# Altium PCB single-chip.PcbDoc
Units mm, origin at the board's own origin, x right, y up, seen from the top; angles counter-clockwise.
Board outline 125 x 86.13 mm, 4 copper layers (Top Layer, POWER, GND, Bottom Layer), stack 0.569 mm thick; 50 components, 172 nets, 486 pads, 32 vias.
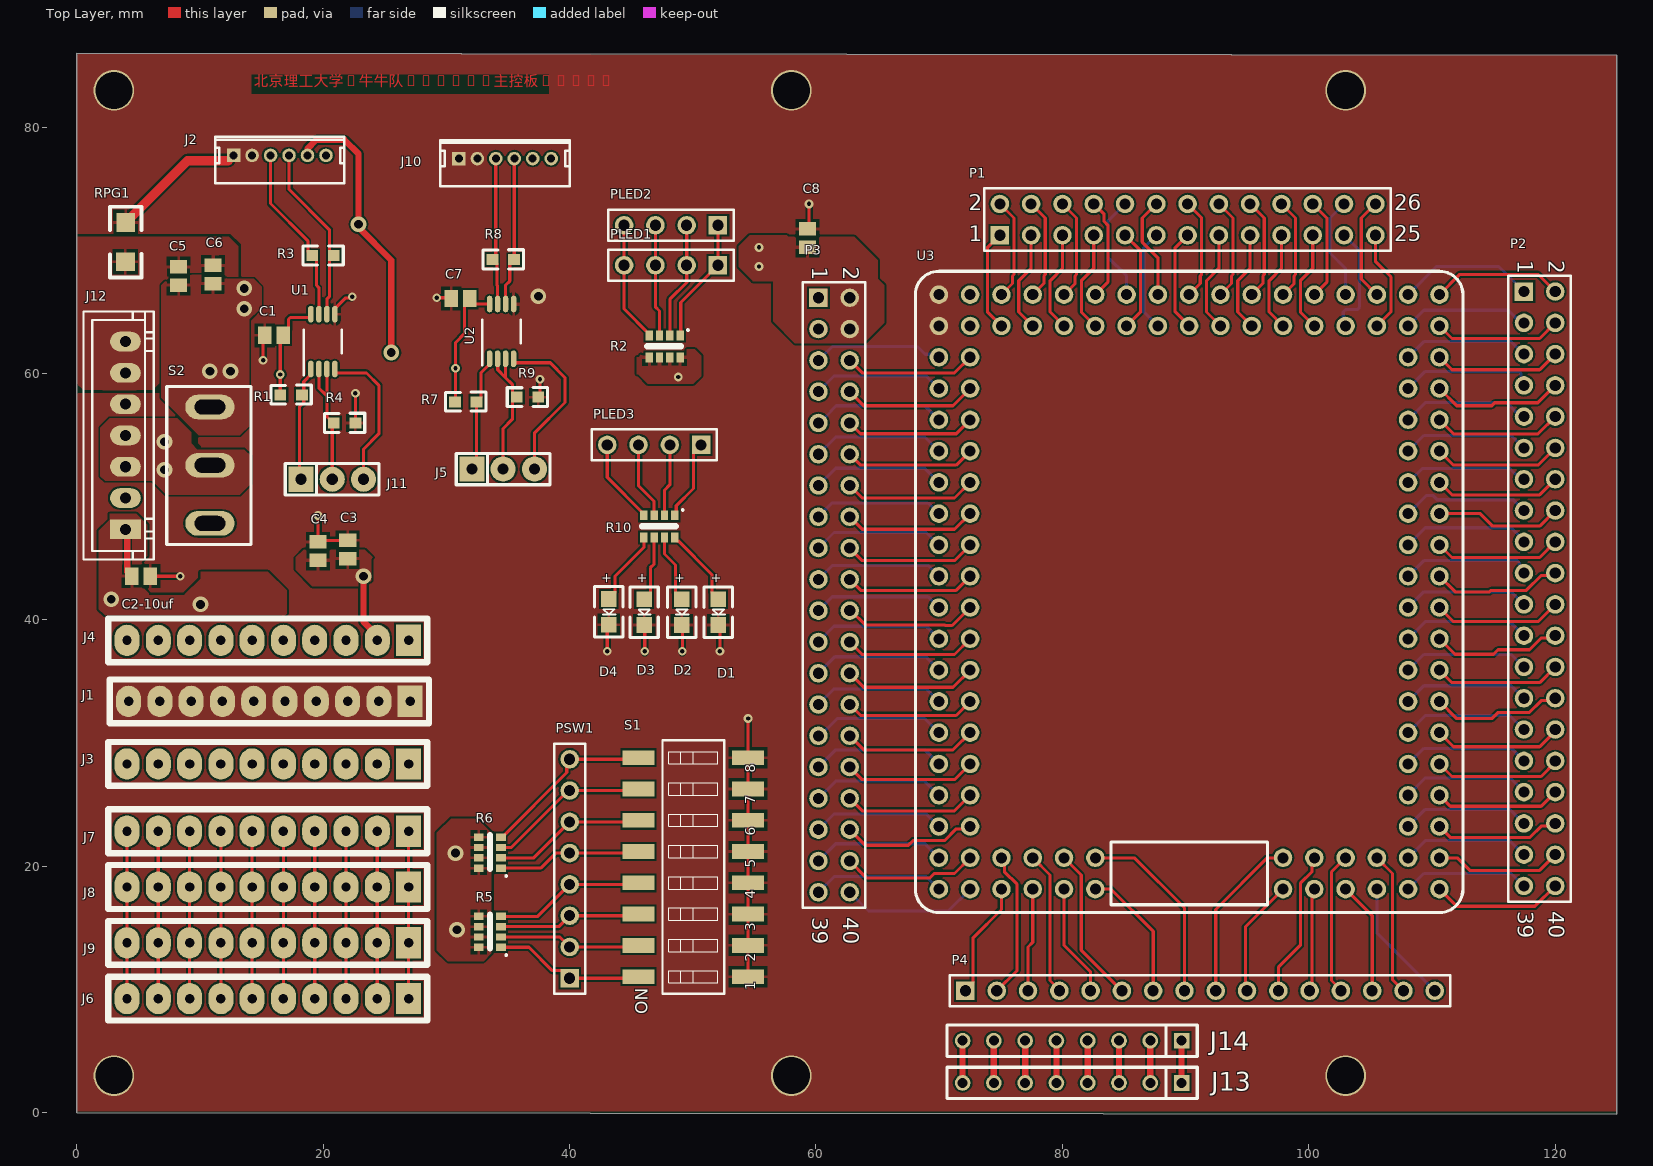
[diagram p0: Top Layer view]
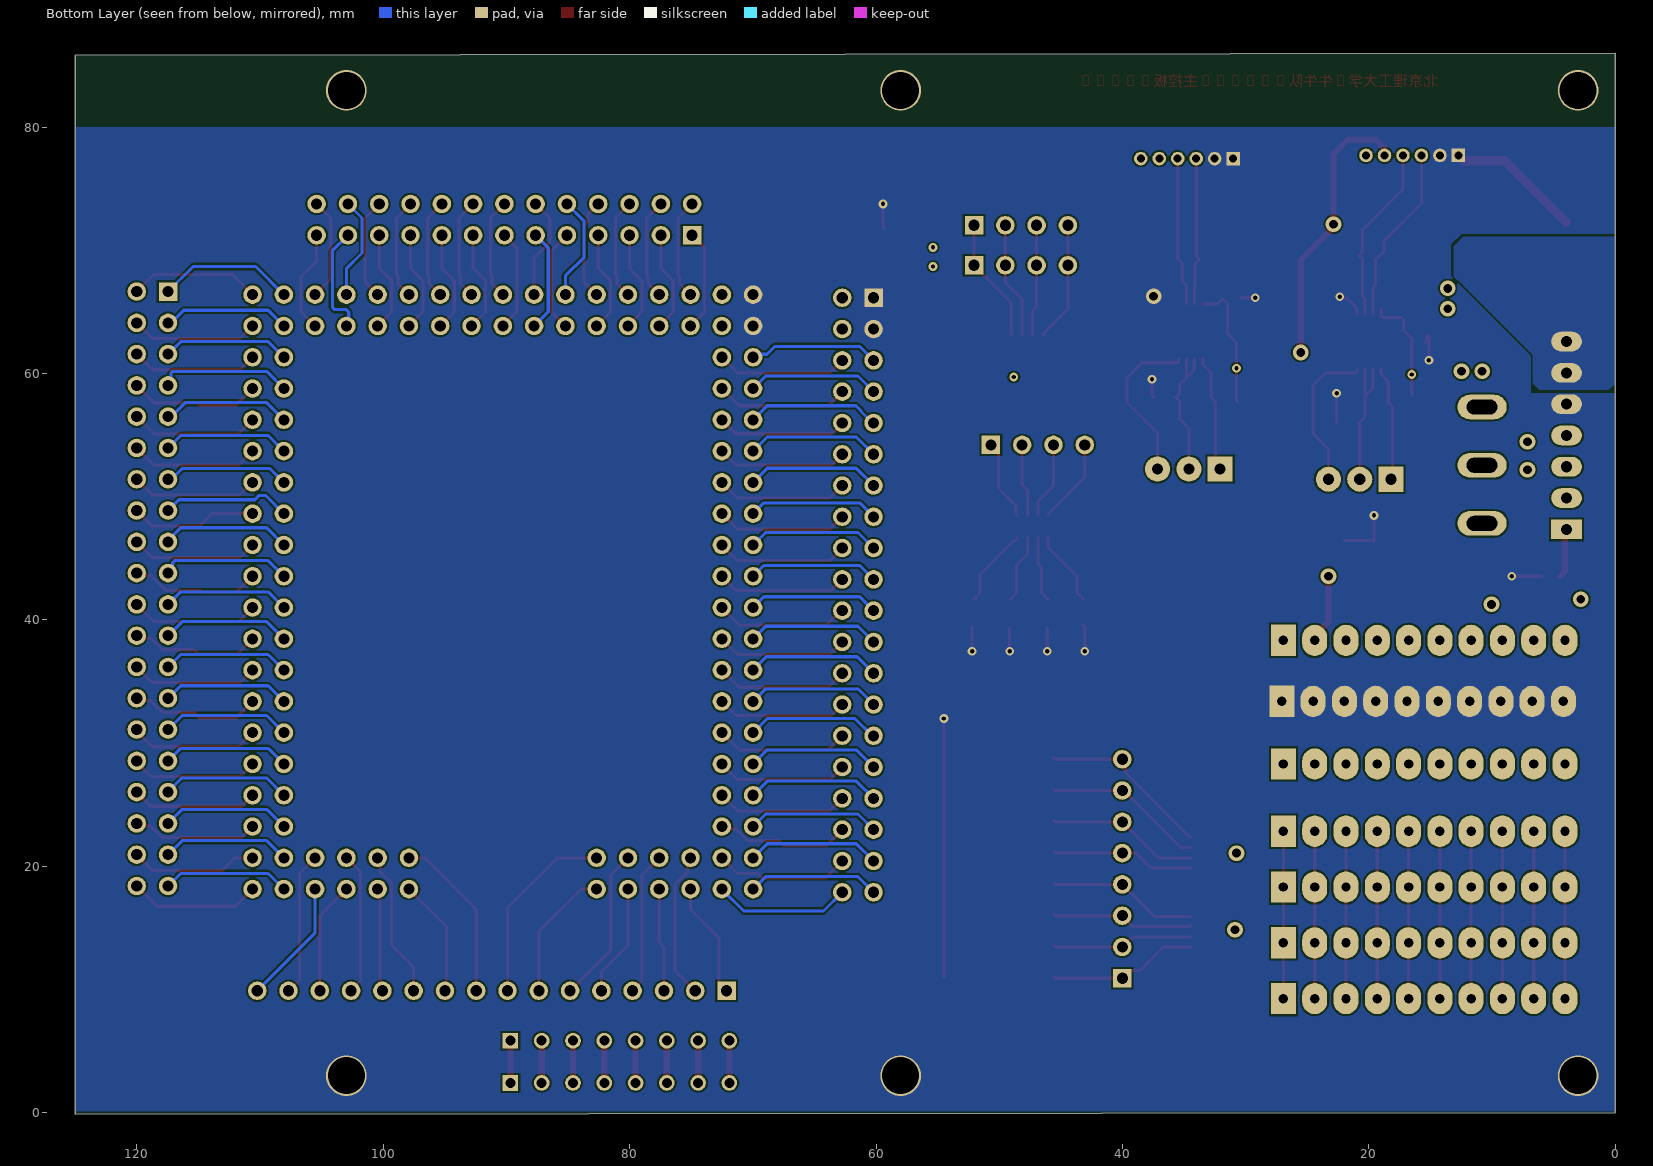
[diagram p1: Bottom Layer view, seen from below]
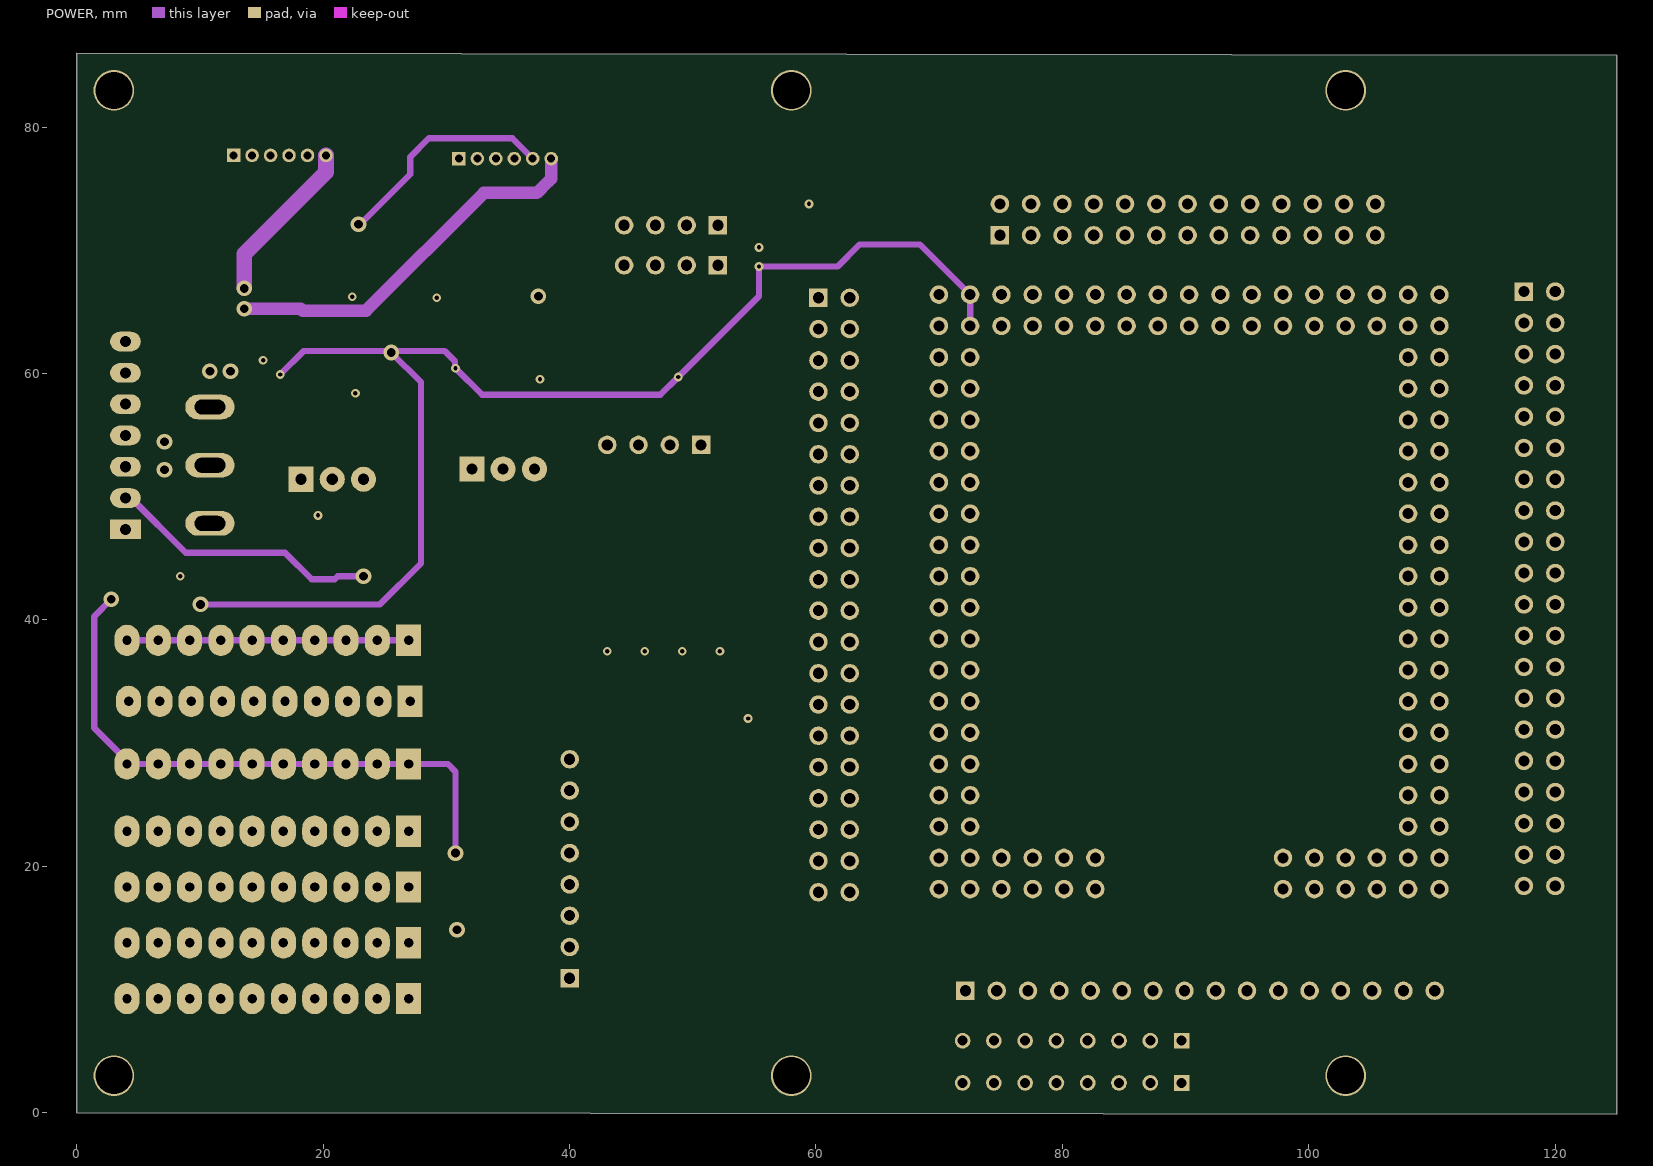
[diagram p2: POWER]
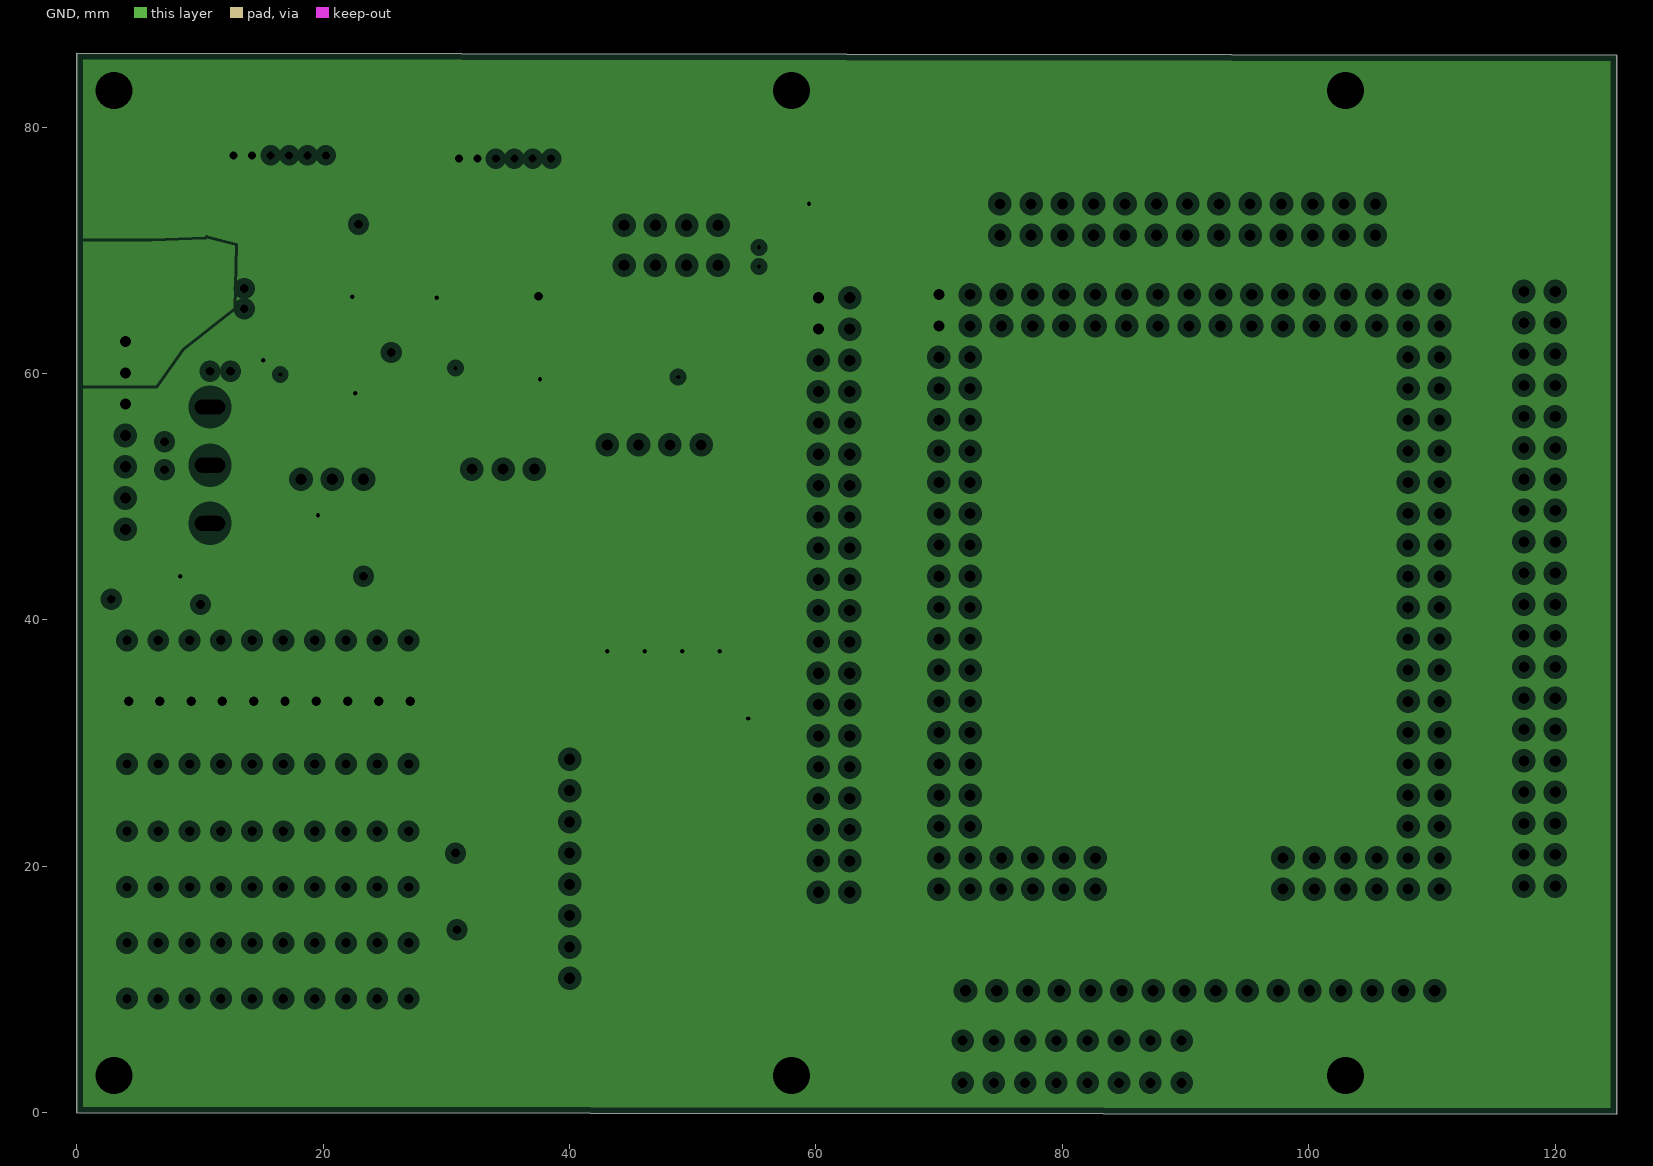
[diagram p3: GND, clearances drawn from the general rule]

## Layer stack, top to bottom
Top Solder: solder mask 0.0102, Solder Resist, Dk 3.5
Top Layer: signal copper 0.0356
Dielectric 2: prepreg 0.0711, PP-006, Dk 4.1
POWER: signal copper 0.0178
Dielectric 3: prepreg 0.0711, PP-006, Dk 4.1
GND: plane copper 0.0178, net (Multiple Nets)
Dielectric 1: dielectric 0.32, FR-4, Dk 4.8
Bottom Layer: signal copper 0.0356
Bottom Solder: solder mask 0.0102, Solder Resist, Dk 3.5

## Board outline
0,0 125,-0.132 125,85.868 0,86

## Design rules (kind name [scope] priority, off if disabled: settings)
Clearance [All] p1: gap=0.152 ignorepadtopadclearanceinfootprint=TRUE
MinimumSolderMaskSliver [All] p1: minsoldermaskwidth=0.051
PlaneClearance [All] p1: clearance=0.508
PlaneConnect [All] p1: planeconnectstyle=Direct reliefexpansion=0.508 reliefentries=4 reliefconductorwidth=0.254 reliefairgap=0.254
PolygonConnect [All] p1: thpad.connectstyle=Direct thpad.reliefconductorwidth=0.254 thpad.reliefentries=4 thpad.polygonreliefangle="90 Angle" thpad.airgapwidth=0.254 smdpad.connectstyle=Relief smdpad.reliefconductorwidth=0.254 smdpad.reliefentries=4 smdpad.polygonreliefangle="90 Angle" smdpad.airgapwidth=0.254 via.connectstyle=Direct via.reliefconductorwidth=0.254 via.reliefentries=4 via.polygonreliefangle="90 Angle" via.airgapwidth=0.254
RoutingVias [All] p1: holewidth=0.356 width=0.711 viastyle="Through Hole" minholewidth=0.152 minwidth=0.152 maxholewidth=3 maxwidth=5
SilkToSilkClearance [All] p1: silktosilkclearance=0.051
SilkToSolderMaskClearance [IsPad] p1: minsilkscreentomaskgap=0.051 clearancetoexposedcopper=TRUE
SolderMaskExpansion [All] p1: expansion=0.102
Width [All] p1: maxlimit=2.54 minlimit=0.254 preferedwidth=0.508 toplayer_maxwidth=1.016 toplayer_prefwidth=0.254 bottomlayer_maxwidth=1.016 bottomlayer_prefwidth=0.254 minimp=50.000000 maximp=50.000000 favimp=50.000000
25 further rules are at their usual default settings.

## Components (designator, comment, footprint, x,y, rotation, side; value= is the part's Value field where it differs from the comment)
C1 "Cap" C0805 16.002,63.109 r0 top value=0.2uF
C2-10uf "Cap" C0805 5.195,43.551 r180 top value=10uF
C3 "Cap" C0805 21.983,45.71 r270 top value=10uF
C4 "Cap" C0805 19.57,45.583 r270 top value=0.1uF
C5 "Cap" C0805 8.255,67.935 r270 top value=10uF
C6 "Cap" C0805 11.049,68.05 r270 top value=100nF
C7 "Cap" C0805 31.127,66.096 r0 top value=0.2uF
C8 "Cap" C0805 59.309,70.995 r270 top value=0.1uF
D1 "LED0" LED0805 52.065,41.679 r270 top
D2 "LED0" LED0805 49.102,41.679 r270 top
D3 "LED0" LED0805 46.049,41.679 r270 top
D4 "LED0" LED0805 43.175,41.704 r270 top
J1 "PIN10" SIP10 27.051,33.391 r180 top
J2 "PIN6" ZH1.5-LI-6P 16.468,77.714 r0 top
J3 "PIN10" SIP10 26.924,28.311 r180 top
J4 "PIN10" SIP10 26.924,38.344 r180 top
J5 "PIN3" SIP3 32.06,52.253 r0 top
J6 "PIN10" SIP10 26.924,9.261 r180 top
J7 "PIN10" SIP10 26.924,22.85 r180 top
J8 "PIN10" SIP10 26.924,18.32 r180 top
J9 "PIN10" SIP10 26.924,13.791 r180 top
J10 "PIN6" ZH1.5-LI-6P 34.754,77.46 r0 top
J11 "PIN3" SIP3 18.186,51.425 r0 top
J12 "PIN7" XH7-2.54 3.937,54.981 r90 top
J13 "PIN8" SIP8 89.68,2.413 r180 top
J14 "PIN8" SIP8 89.68,5.842 r180 top
P1 "Header 13X2" HDR2X13 74.93,71.237 r0 top
P2 "Header 20X2" HDR2X20 117.475,66.665 r270 top
P3 "Header 20X2" HDR2X20 60.198,66.157 r270 top
P4 "Header 16" HDR1X16 72.136,9.896 r0 top
PLED1 "Header 4" HDR1X4 52.043,68.797 r180 top
PLED2 "Header 4" HDR1X4 52.043,72.045 r180 top
PLED3 "Header 4" HDR1X4 50.673,54.219 r180 top
PSW1 "Header 8" HDR1X8 40.005,10.912 r90 top
R1 "Res2" R0603 18.263,58.283 r180 top value=10K
R2 "Res Pack4" "R0603 组排" 48.971,63.109 r270 top value=1K
R3 "Res2" R0603 20.853,69.586 r180 top value=120
R4 "Res2" R0603 22.606,55.997 r180 top value=10K
R5 "Res Pack4" "R0603 组排" 34.417,13.427 r180 top value=2K
R6 "Res Pack4" "R0603 组排" 34.417,19.853 r180 top value=2K
R7 "Res2" R0603 32.441,57.714 r180 top value=10K
R8 "Res2" R0603 35.489,69.271 r180 top value=120
R9 "Res2" R0603 37.455,58.095 r180 top value=10K
R10 "Res Pack4" "R0603 组排" 48.539,48.504 r270 top value=2K
RPG1 "Res2" R1206 3.886,70.475 r270 top value=0Ω
S1 "SW DIP-8" DIP_SW_8WAY_SMD 50.038,19.929 r90 top
S2 "SW-SPDT" SW-TO3 10.795,52.568 r0 top
U1 "THVD1450DGK" DGK0008A_N 19.964,62.601 r90 top value=Value
U2 "THVD1450DGK" DGK0008A_N 34.473,63.429 r90 top value=Value
U3 "TC264_CoreBoard" TC264_CoreBoard 69.977,66.411 r0 top

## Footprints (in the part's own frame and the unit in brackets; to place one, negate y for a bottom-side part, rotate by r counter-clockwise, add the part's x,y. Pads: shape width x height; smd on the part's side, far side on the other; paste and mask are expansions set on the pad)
C0805 [mm] "Chip Capacitor, Body 2.0x1.3mm, IPC High Density"
  rect 1.1x1.4 smd: 1(-0.75,0) 2(0.75,0)
  body extent -1.1,-0.72 1.1,0.72, height 1.4
DGK0008A_N [mm]
  oval 1.35x0.45 smd paste+0 mask+0: 1(-2.225,0.975) 2(-2.225,0.325) 3(-2.225,-0.325) 4(-2.225,-0.975) 5(2.225,-0.975) 6(2.225,-0.325) 7(2.225,0.325) 8(2.225,0.975)
  silkscreen extent -2.75,-1.55 0.95,1.55, body extent 0,0 0.25,0.25, height 0.25
DIP_SW_8WAY_SMD [mm] "DIP Switch; 16 Leads"
  rect 1.2x2.6 smd: 1(-8.89,-4.45) 2(-6.35,-4.45) 3(-3.81,-4.45) 4(-1.27,-4.45) 5(1.27,-4.45) 6(3.81,-4.45) 7(6.35,-4.45) 8(8.89,-4.45) 9(8.89,4.45) 10(6.35,4.45) 11(3.81,4.45) 12(1.27,4.45) 13(-1.27,4.45) 14(-3.81,4.45) 15(-6.35,4.45) 16(-8.89,4.45)
  silkscreen extent -10.29,-2.5 10.31,2.5
HDR1X4 [mm] "Connector; Header; 4 Position"
  rect 1.5x1.5 hole 0.9: 1(0,0)
  round 1.5 hole 0.9: 2(2.54,0) 3(5.08,0) 4(7.62,0)
  silkscreen extent -1.27,-1.27 8.89,1.27
HDR1X8 [mm] "Connector; Header; 8 Position"
  rect 1.5x1.5 hole 0.9: 1(0,0)
  round 1.5 hole 0.9: 2(2.54,0) 3(5.08,0) 4(7.62,0) 5(10.16,0) 6(12.7,0) 7(15.24,0) 8(17.78,0)
  silkscreen extent -1.27,-1.27 19.05,1.27
HDR1X16 [mm] "Connector; Header; 16 Position"
  rect 1.5x1.5 hole 0.9: 1(0,0)
  round 1.5 hole 0.9: 2(2.54,0) 3(5.08,0) 4(7.62,0) 5(10.16,0) 6(12.7,0) 7(15.24,0) 8(17.78,0) 9(20.32,0) 10(22.86,0) 11(25.4,0) 12(27.94,0) 13(30.48,0) 14(33.02,0) 15(35.56,0) 16(38.1,0)
  silkscreen extent -1.27,-1.27 39.37,1.27
HDR2X13 [mm] "Connector; Header; 13x2 Position"
  rect 1.5x1.5 hole 0.9: 1(0,0)
  round 1.5 hole 0.9: 2(0,2.54) 3(2.54,0) 4(2.54,2.54) 5(5.08,0) 6(5.08,2.54) 7(7.62,0) 8(7.62,2.54) 9(10.16,0) 10(10.16,2.54) 11(12.7,0) 12(12.7,2.54) 13(15.24,0) 14(15.24,2.54) 15(17.78,0) 16(17.78,2.54) 17(20.32,0) 18(20.32,2.54) 19(22.86,0) 20(22.86,2.54) 21(25.4,0) 22(25.4,2.54) 23(27.94,0) 24(27.94,2.54) 25(30.48,0) 26(30.48,2.54)
  silkscreen extent -1.27,-1.27 31.75,3.81
HDR2X20 [mm] "Connector; Header; 20x2 Position"
  rect 1.5x1.5 hole 0.9: 1(0,0)
  round 1.5 hole 0.9: 2(0,2.54) 3(2.54,0) 4(2.54,2.54) 5(5.08,0) 6(5.08,2.54) 7(7.62,0) 8(7.62,2.54) 9(10.16,0) 10(10.16,2.54) 11(12.7,0) 12(12.7,2.54) 13(15.24,0) 14(15.24,2.54) 15(17.78,0) 16(17.78,2.54) 17(20.32,0) 18(20.32,2.54) 19(22.86,0) 20(22.86,2.54) 21(25.4,0) 22(25.4,2.54) 23(27.94,0) 24(27.94,2.54) 25(30.48,0) 26(30.48,2.54) 27(33.02,0) 28(33.02,2.54) 29(35.56,0) 30(35.56,2.54) 31(38.1,0) 32(38.1,2.54) 33(40.64,0) 34(40.64,2.54) 35(43.18,0) 36(43.18,2.54) 37(45.72,0) 38(45.72,2.54) 39(48.26,0) 40(48.26,2.54)
  silkscreen extent -1.27,-1.27 49.53,3.81
LED0805 [mm] "1/8W"
  rect 1.27x1.27 smd: 1(0,0) 2(2.09,0.005)
  silkscreen extent -1.01,-1.14 3.1,1.15, body extent 0.05,-0.64 2.03,0.64, height 0.5
R0603 [mil] "1/10W"
  rect 38x35 smd: 1(0,0) 2(69,0)
  silkscreen extent -30,-31 99,30, body extent 4,-16 66,16, height 18
"R0603 组排" [mm]
  rect 0.8x0.6 smd: 1(0,0) 2(0,-0.838) 3(0,-1.676) 4(0,-2.514) 5(1.8,-2.514) 6(1.8,-1.676) 7(1.8,-0.838) 8(1.8,0)
  silkscreen extent -0.46,-2.67 0.89,0.66, body extent 0.09,-2.87 1.69,0.33, height 0.55
R1206 [mil] "1/4W"
  rect 60x60 smd: 1(-71,3) 2(55,2)
  silkscreen extent -121,-47 105,53, body extent -71,-29 55,33, height 24
SIP3 [mil]
  rect 80x80 hole 35.43: 1(0,0)
  round 80 hole 35.43: 2(100,0) 3(200,0)
  silkscreen extent -50,-50 250,50
SIP8 [mil]
  rect 50x50 hole 32: 1(0,0)
  round 50 hole 32: 2(100,0) 3(200,0) 4(300,0) 5(400,0) 6(500,0) 7(600,0) 8(700,0)
  silkscreen extent -50,-50 750,50
SIP10 [mil]
  rect 80x100 hole 30: 1(0,0)
  oval 80x100 hole 30: 2(100,0) 3(200,0) 4(300,0) 5(400,0) 6(500,0) 7(600,0) 8(700,0) 9(800,0) 10(900,0)
  silkscreen extent -60,-70 960,70
SW-TO3 [mm]
  oval 4x2 hole 1.2 slot 2.5 at 0 deg: 1(0,-4.724) 2(0,0) 3(0,4.724)
  silkscreen extent -3.5,-6.43 3.33,6.39, body extent -3.43,-6.36 3.43,6.35, height 28.55
TC264_CoreBoard [mm] "逐飞科技TC264核心板"
  round 1.5 hole 0.9: 1(0,0) 2(2.54,0) 3(0,-2.54) 4(2.54,-2.54) 5(0,-5.08) 6(2.54,-5.08) 7(0,-7.62) 8(2.54,-7.62) 9(0,-10.16) 10(2.54,-10.16) 11(0,-12.7) 12(2.54,-12.7) 13(0,-15.24) 14(2.54,-15.24) 15(0,-17.78) 16(2.54,-17.78) 17(0,-20.32) 18(2.54,-20.32) 19(0,-22.86) 20(2.54,-22.86) 21(0,-25.4) 22(2.54,-25.4) 23(0,-27.94) 24(2.54,-27.94) 25(0,-30.48) 26(2.54,-30.48) 27(0,-33.02) 28(2.54,-33.02) 29(0,-35.56) 30(2.54,-35.56) 31(0,-38.1) 32(2.54,-38.1) 33(0,-40.64) 34(2.54,-40.64) 35(0,-43.18) 36(2.54,-43.18) 37(0,-45.72) 38(2.54,-45.72) 39(0,-48.26) 40(2.54,-48.26) 41(5.08,-48.26) 42(5.08,-45.72) 43(7.62,-48.26) 44(7.62,-45.72) 45(10.16,-48.26) 46(10.16,-45.72) 47(12.7,-48.26) 48(12.7,-45.72) 49(27.94,-45.72) 50(27.94,-48.26) 51(30.48,-45.72) 52(30.48,-48.26) 53(33.02,-45.72) 54(33.02,-48.26) 55(35.56,-45.72) 56(35.56,-48.26) 57(38.1,-48.26) 58(40.64,-48.26) 59(38.1,-45.72) 60(40.64,-45.72) 61(38.1,-43.18) 62(40.64,-43.18) 63(38.1,-40.64) 64(40.64,-40.64) 65(38.1,-38.1) 66(40.64,-38.1) 67(38.1,-35.56) 68(40.64,-35.56) 69(38.1,-33.02) 70(40.64,-33.02) 71(38.1,-30.48) 72(40.64,-30.48) 73(38.1,-27.94) 74(40.64,-27.94) 75(38.1,-25.4) 76(40.64,-25.4) 77(38.1,-22.86) 78(40.64,-22.86) 79(38.1,-20.32) 80(40.64,-20.32) 81(38.1,-17.78) 82(40.64,-17.78) 83(38.1,-15.24) 84(40.64,-15.24) 85(38.1,-12.7) 86(40.64,-12.7) 87(38.1,-10.16) 88(40.64,-10.16) 89(38.1,-7.62) 90(40.64,-7.62) 91(38.1,-5.08) 92(40.64,-5.08) 93(38.1,-2.54) 94(40.64,-2.54) 95(38.1,0) 96(40.64,0) 97(35.56,-2.54) 98(35.56,0) 99(33.02,-2.54) 100(33.02,0) 101(30.48,-2.54) 102(30.48,0) 103(27.94,-2.54) 104(27.94,0) 105(25.4,-2.54) 106(25.4,0) 107(22.86,-2.54) 108(22.86,0) 109(20.32,-2.54) 110(20.32,0) 111(17.78,-2.54) 112(17.78,0) 113(15.24,-2.54) 114(15.24,0) 115(12.7,-2.54) 116(12.7,0) 117(10.16,-2.54) 118(10.16,0) 119(7.62,-2.54) 120(7.62,0) 121(5.08,-2.54) 122(5.08,0)
  silkscreen extent -1.91,-50.16 42.55,1.91
XH7-2.54 [mm]
  rect 1.6x2.5 hole 0.9: 1(-7.62,0)
  oval 1.6x2.5 hole 0.9: 2(-5.08,0) 3(-2.54,0) 4(0,0) 5(2.54,0) 6(5.08,0) 7(7.62,0)
  silkscreen extent -10.07,-2.3 10.07,3.4
ZH1.5-LI-6P [mm] "长：10.5，宽：3.65，高：4.55  淘宝ID:黄晶宝石   店铺网址:https://shop463601444.taobao.com"
  rect 1.1x1.1 hole 0.65: 1(-3.75,0)
  round 1.1 hole 0.65: 2(-2.25,0) 3(-0.75,0) 4(0.75,0) 5(2.25,0) 6(3.75,0)
  silkscreen extent -5.25,-2.25 5.25,1.5, body extent -5.25,-2.15 5.25,1.5, height 4.6

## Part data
C1 C2-10uf C3 C4 C5 C6 C7 C8: "Capacitor"
D1 D2 D3 D4: "Typical INFRARED GaAs LED"
P1: "Header, 13-Pin, Dual row"
P2 P3: "Header, 20-Pin, Dual row"
P4: "Header, 16-Pin"
PLED1 PLED2 PLED3: "Header, 4-Pin"
PSW1: "Header, 8-Pin"
R1 R3 R4 R7 R8 R9 RPG1: "Resistor"
R2 R5 R6 R10: library part Res_x4, "Isolated Resistor Network"
S1: "DIP Switch, 8 Position, SPST"
S2: "SPDT Subminiature Toggle Switch, Right Angle Mounting, Vertical Actuation"
U1 U2: "No Description Available", Manufacturer="Texas Instruments", PartNumber=THVD1450DGKR
U3: "逐飞科技TC264核心板"

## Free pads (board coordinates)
  round 3.3 hole 3: 4(3,3) 4(3,83) 4(58,3) 4(58,83) 4(103,3) 4(103,83)

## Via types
v1: diameter 0.711, hole 0.356, Top Layer to Bottom Layer, 18 vias
v2: diameter 1.27, hole 0.711, Top Layer to Bottom Layer, 14 vias

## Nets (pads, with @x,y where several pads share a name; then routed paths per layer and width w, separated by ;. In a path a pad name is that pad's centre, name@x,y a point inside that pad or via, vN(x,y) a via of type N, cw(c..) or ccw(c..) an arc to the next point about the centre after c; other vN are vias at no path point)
A1: J2.4 R3.1 U1.6 | length 14.6
  Top Layer w0.254: J2.4 17.218,74.974 20.498,71.694 20.498,69.904 20.815,69.586 20.498,69.269 20.498,66.254 20.289,66.045 U1.6
A2: J10.4 R8.1 U2.6 | length 12.1
  Top Layer w0.254: U2.6 34.798,67.173 35.133,67.508 35.133,68.953 35.451,69.271 R8.1 35.504,69.286 J10.4
B1: J2.3 R3.2 U1.7 | length 14.6
  Top Layer w0.254: J2.3 15.718,73.807 18.745,70.78 18.745,69.904 19.063,69.586 R3.2 19.139,69.586 19.456,69.269 19.456,67.157 19.639,66.974 U1.7
B2: J10.3 R8.2 U2.7 | length 12.1
  Top Layer w0.254: J10.3 34.004,69.539 R8.2 33.774,69.271 34.092,68.953 34.092,67.212 34.148,67.156 U2.7
DIR1: J11.2 R4.2 U1.2 U1.3 | length 11.7
  Top Layer w0.254: U1.2 19.639,58.837 20.193,58.283 20.289,58.283 ; U1.3 20.289,58.283 ; J11.2 20.726,55.87 R4.2 20.815,55.997 20.289,56.523 20.289,58.283
DIR2: J5.2 R9.2 U2.2 U2.3 | length 11.6
  Top Layer w0.254: U2.2 34.163,61.189 34.163,60.315 34.798,59.68 ; J5.2 34.6,55.545 35.346,56.291 35.346,57.777 R9.2@35.664,58.095 ; U2.3 34.798,59.68 ; R9.2 R9.2@35.664,58.095 ; 34.798,59.68 35.346,59.132 35.346,58.412 R9.2@35.664,58.095
LED0: PLED3.1 R10.1 | length 6.6
  Top Layer w0.254: R10.1 48.66,48.625 48.66,49.285 50.05,50.675 50.05,53.596 PLED3.1
LED1: PLED3.2 R10.2 | length 5.9
  Top Layer w0.254: R10.2 47.701,50.536 48.133,50.968 PLED3.2
LED2: PLED3.3 R10.3 | length 6.2
  Top Layer w0.254: PLED3.3 45.593,50.89 46.863,49.62 R10.3
LED3: PLED3.4 R10.4 | length 6.9
  Top Layer w0.254: PLED3.4 43.053,51.576 46.025,48.604 R10.4
NetD1_1: D1.1 R10.8 | length 6.5
  Top Layer w0.254: R10.8 48.539,46.604 48.712,46.431 48.812,46.431 51.557,43.686 51.557,42.187 D1.1
NetD2_1: D2.1 R10.7 | length 5.6
  Top Layer w0.254: R10.7 47.701,45.353 48.594,44.461 48.594,42.187 D2.1
NetD3_1: D3.1 R10.6 | length 5.4
  Top Layer w0.254: D3.1 46.557,42.187 46.557,44.234 46.863,44.541 R10.6
NetD4_1: D4.1 R10.5 | length 6.2
  Top Layer w0.254: D4.1 43.683,42.212 43.683,43.546 46.025,45.888 R10.5
NetJ6_1: J6.1 J7.1 J8.1 J9.1 | length 13.6
  Top Layer w0.254: J6.1 J9.1 J8.1 J7.1
NetJ6_2: J6.2 J7.2 J8.2 J9.2 | length 13.6
  Top Layer w0.254: J6.2 J9.2 J8.2 J7.2
NetJ6_3: J6.3 J7.3 J8.3 J9.3 | length 13.6
  Top Layer w0.254: J6.3 J9.3 J8.3 J7.3
NetJ6_4: J6.4 J7.4 J8.4 J9.4 | length 13.6
  Top Layer w0.254: J6.4 J9.4 J8.4 J7.4
NetJ6_5: J6.5 J7.5 J8.5 J9.5 | length 13.6
  Top Layer w0.254: J6.5 J9.5 J8.5 J7.5
NetJ6_6: J6.6 J7.6 J8.6 J9.6 | length 13.6
  Top Layer w0.254: J6.6 J9.6 J8.6 J7.6
NetJ6_7: J6.7 J7.7 J8.7 J9.7 | length 13.6
  Top Layer w0.254: J6.7 J9.7 J8.7 J7.7
NetJ6_8: J6.8 J7.8 J8.8 J9.8 | length 13.6
  Top Layer w0.254: J6.8 J9.8 J8.8 J7.8
NetJ6_9: J6.9 J7.9 J8.9 J9.9 | length 13.6
  Top Layer w0.254: J6.9 J9.9 J8.9 J7.9
NetJ6_10: J6.10 J7.10 J8.10 J9.10 | length 13.6
  Top Layer w0.254: J6.10 J9.10 J8.10 J7.10
NetJ13_1: J13.1 J14.1 | length 3.4
  Top Layer w0.508: J13.1 J14.1
NetJ13_2: J13.2 J14.2 | length 3.4
  Top Layer w0.508: J13.2 J14.2
NetJ13_3: J13.3 J14.3 | length 3.4
  Top Layer w0.508: J13.3 J14.3
NetJ13_4: J13.4 J14.4 | length 3.4
  Top Layer w0.508: J13.4 J14.4
NetJ13_5: J13.5 J14.5 | length 3.4
  Top Layer w0.508: J13.5 J14.5
NetJ13_6: J13.6 J14.6 | length 3.4
  Top Layer w0.508: J13.6 J14.6
NetJ13_7: J13.7 J14.7 | length 3.4
  Top Layer w0.508: J13.7 J14.7
NetJ13_8: J13.8 J14.8 | length 3.4
  Top Layer w0.508: J13.8 J14.8
NetP1_1: P1.1 U3.121 | length 8.3
  Top Layer w0.254: P1.1 73.914,70.221 73.914,65.014 U3.121
NetP1_2: P1.2 U3.122 | length 8.3
  Top Layer w0.254: P1.2 76.073,72.634 76.073,68.05 75.958,67.935 75.958,67.312 U3.122
NetP1_3: P1.3 U3.119 | length 8.3
  Top Layer w0.254: P1.3 77.47,68.558 76.466,67.554 76.466,65.002 U3.119
NetP1_4: P1.4 U3.120 | length 8.3
  Top Layer w0.254: P1.4 78.613,72.634 78.613,68.05 78.498,67.935 78.498,67.312 U3.120
NetP1_5: P1.5 U3.117 | length 8.3
  Top Layer w0.254: P1.5 80.01,68.558 79.006,67.554 79.006,65.002 U3.117
NetP1_6: P1.6 U3.118 | length 8.3
  Top Layer w0.254: P1.6 81.153,72.634 81.153,68.05 81.038,67.935 81.038,67.312 U3.118
NetP1_7: P1.7 U3.115 | length 8.3
  Top Layer w0.254: P1.7 82.55,68.558 81.546,67.554 81.546,65.002 U3.115
NetP1_8: P1.8 U3.116 | length 8.3
  Top Layer w0.254: P1.8 83.388,72.939 83.388,72.355 83.693,72.05 83.693,67.427 U3.116
NetP1_9: P1.9 U3.113 | length 8.4
  Top Layer w0.254: P1.9 86.36,69.967 86.36,65.014 U3.113
NetP1_10: P1.10 U3.114 | length 8.6
  Bottom Layer w0.254: P1.10 83.693,72.38 83.693,69.459 85.217,67.935 U3.114
NetP1_11: P1.11 U3.111 | length 8.3
  Bottom Layer w0.254: P1.11 86.614,70.221 86.614,65.014 U3.111
NetP1_12: P1.12 U3.112 | length 8.4
  Top Layer w0.254: P1.12 86.487,72.634 86.487,70.678 87.757,69.408 U3.112
NetP1_13: P1.13 U3.109 | length 8.3
  Top Layer w0.254: P1.13 89.154,70.221 89.154,65.014 U3.109
NetP1_14: P1.14 U3.110 | length 8.3
  Top Layer w0.254: P1.14 91.313,72.634 91.313,68.05 91.198,67.935 91.198,67.312 U3.110
NetP1_15: P1.15 U3.107 | length 8.3
  Top Layer w0.254: P1.15 92.71,68.558 91.706,67.554 91.706,65.002 U3.107
NetP1_16: P1.16 U3.108 | length 8.3
  Top Layer w0.254: P1.16 93.853,72.634 93.853,68.05 93.738,67.935 93.738,67.312 U3.108
NetP1_17: P1.17 U3.105 | length 8.3
  Top Layer w0.254: P1.17 95.25,68.558 94.246,67.554 94.246,65.002 U3.105
NetP1_18: P1.18 U3.106 | length 8.3
  Top Layer w0.254: P1.18 96.393,72.634 96.393,68.05 96.278,67.935 96.278,67.312 U3.106
NetP1_19: P1.19 U3.103 | length 8.3
  Top Layer w0.254: P1.19 97.79,68.558 96.786,67.554 96.786,65.002 U3.103
NetP1_20: P1.20 U3.104 | length 8.3
  Top Layer w0.254: P1.20 98.933,72.634 98.933,68.05 98.818,67.935 98.818,67.312 U3.104
NetP1_21: P1.21 U3.101 | length 8.3
  Top Layer w0.254: P1.21 100.33,68.558 99.326,67.554 99.326,65.002 U3.101
NetP1_22: P1.22 U3.102 | length 8.3
  Top Layer w0.254: P1.22 101.473,72.634 101.473,67.427 U3.102
NetP1_23: P1.23 U3.99 | length 9.1
  Bottom Layer w0.254: P1.23 104.14,69.967 104.14,65.395 103.944,65.199 103.003,65.199 102.807,65.002 102.807,64.061 U3.99
NetP1_24: P1.24 U3.100 | length 8.4
  Bottom Layer w0.254: P1.24 101.727,72.634 101.727,69.789 102.997,68.519 U3.100
NetP1_25: P1.25 U3.97 | length 8.4
  Top Layer w0.254: P1.25 105.41,69.129 106.68,67.859 106.68,65.014 U3.97
NetP1_26: P1.26 U3.98 | length 8.4
  Top Layer w0.254: P1.26 104.267,72.634 104.267,67.681 U3.98
NetP2_1: P2.1 U3.95 | length 11.2
  Bottom Layer w0.254: U3.95 110.363,68.697 115.443,68.697 P2.1
NetP2_2: P2.2 U3.96 | length 10.7
  Top Layer w0.254: U3.96 112.268,68.062 118.618,68.062 P2.2
NetP2_3: P2.3 U3.93 | length 10.3
  Bottom Layer w0.254: U3.93 109.347,65.141 116.205,65.141 117.221,64.125 P2.3
NetP2_4: P2.4 U3.94 | length 10.3
  Top Layer w0.254: U3.94 111.633,62.855 118.745,62.855 P2.4
NetP2_5: P2.5 U3.91 | length 10.3
  Bottom Layer w0.254: U3.91 109.347,62.601 116.459,62.601 P2.5
NetP2_6: P2.6 U3.92 | length 10.3
  Top Layer w0.254: U3.92 111.633,60.315 118.745,60.315 P2.6
NetP2_7: P2.7 U3.89 | length 10.9
  Bottom Layer w0.254: U3.89 109.474,60.188 117.094,60.188 117.237,60.045 117.237,59.283 P2.7
NetP2_8: P2.8 U3.90 | length 10.7
  Top Layer w0.254: U3.90 112.014,57.394 114.858,57.394 115.1,57.636 118.606,57.636 P2.8
NetP2_9: P2.9 U3.87 | length 10.5
  Bottom Layer w0.254: U3.87 109.474,57.648 116.078,57.648 117.221,56.505 P2.9
NetP2_10: P2.10 U3.88 | length 10.5
  Top Layer w0.254: U3.88 111.76,55.108 118.618,55.108 P2.10
NetP2_11: P2.11 U3.85 | length 10.3
  Bottom Layer w0.254: U3.85 109.347,54.981 116.459,54.981 P2.11
NetP2_12: P2.12 U3.86 | length 10.5
  Top Layer w0.254: U3.86 111.76,52.568 118.618,52.568 P2.12
NetP2_13: P2.13 U3.83 | length 10.4
  Bottom Layer w0.254: U3.83 108.331,51.171 108.331,51.425 109.208,52.302 116.32,52.302 117.197,51.425 P2.13
NetP2_14: P2.14 U3.84 | length 10.3
  Top Layer w0.254: U3.84 111.633,50.155 118.745,50.155 P2.14
NetP2_15: P2.15 U3.81 | length 10.5
  Bottom Layer w0.254: U3.81 109.563,50.117 110.071,50.117 110.427,49.762 116.598,49.762 P2.15
NetP2_16: P2.16 U3.82 | length 10.3
  Top Layer w0.254: U3.82 113.935,48.631 114.951,47.615 118.745,47.615 P2.16
NetP2_17: P2.17 U3.79 | length 10.5
  Bottom Layer w0.254: U3.79 109.474,47.488 116.459,47.488 117.475,46.472 P2.17
NetP2_18: P2.18 U3.80 | length 10.3
  Top Layer w0.254: U3.80 111.633,45.075 118.745,45.075 P2.18
NetP2_19: P2.19 U3.77 | length 10.6
  Bottom Layer w0.254: U3.77 109.347,44.821 116.945,44.821 117.094,44.672 117.094,44.523 117.475,44.142 P2.19
NetP2_20: P2.20 U3.78 | length 10.6
  Top Layer w0.254: U3.78 111.887,42.281 114.681,42.281 114.808,42.408 117.677,42.408 118.884,43.615 119.825,43.615 P2.20
NetP2_21: P2.21 U3.75 | length 10.3
  Bottom Layer w0.254: U3.75 109.347,42.281 116.459,42.281 P2.21
NetP2_22: P2.22 U3.76 | length 10.6
  Top Layer w0.254: U3.76 111.76,39.868 118.618,39.868 119.761,41.011 119.761,41.265 P2.22
NetP2_23: P2.23 U3.73 | length 10.6
  Bottom Layer w0.254: U3.73 108.293,38.471 108.293,38.687 109.474,39.868 116.332,39.868 P2.23
NetP2_24: P2.24 U3.74 | length 10.5
  Top Layer w0.254: U3.74 111.875,37.213 114.998,37.213 115.368,37.582 117.931,37.582 118.884,38.535 119.825,38.535 P2.24
NetP2_25: P2.25 U3.71 | length 10.3
  Bottom Layer w0.254: U3.71 109.347,37.201 116.459,37.201 P2.25
NetP2_26: P2.26 U3.72 | length 10.3
  Top Layer w0.254: U3.72 111.633,34.915 118.745,34.915 P2.26
NetP2_27: P2.27 U3.69 | length 10.3
  Bottom Layer w0.254: U3.69 109.347,34.661 116.459,34.661 P2.27
NetP2_28: P2.28 U3.70 | length 10.7
  Top Layer w0.254: U3.70 112.014,31.994 114.871,31.994 115.379,32.502 117.931,32.502 118.884,33.455 119.825,33.455 P2.28
NetP2_29: P2.29 U3.67 | length 10.5
  Bottom Layer w0.254: U3.67 109.474,32.248 116.332,32.248 P2.29
NetP2_30: P2.30 U3.68 | length 10.5
  Top Layer w0.254: U3.68 111.76,29.708 118.745,29.708 120.015,30.978 P2.30
NetP2_31: P2.31 U3.65 | length 10.5
  Bottom Layer w0.254: U3.65 108.293,28.311 108.293,28.527 109.347,29.581 116.459,29.581 P2.31
NetP2_32: P2.32 U3.66 | length 10.4
  Top Layer w0.254: U3.66 111.633,27.295 118.872,27.295 120.015,28.438 P2.32
NetP2_33: P2.33 U3.63 | length 10.5
  Bottom Layer w0.254: U3.63 109.486,27.18 116.344,27.18 117.475,26.049 P2.33
NetP2_34: P2.34 U3.64 | length 10.4
  Top Layer w0.254: U3.64 110.871,25.771 110.871,25.517 111.506,24.882 118.872,24.882 P2.34
NetP2_35: P2.35 U3.61 | length 10.6
  Bottom Layer w0.254: U3.61 108.331,23.231 108.331,23.485 109.474,24.628 116.332,24.628 P2.35
NetP2_36: P2.36 U3.62 | length 10.4
  Top Layer w0.254: U3.62 110.871,23.231 110.871,22.977 111.494,22.354 117.97,22.354 118.884,23.268 119.798,23.268 P2.36
NetP2_37: P2.37 U3.59 | length 10.6
  Bottom Layer w0.254: U3.59 108.331,20.691 108.331,20.945 109.474,22.088 116.332,22.088 P2.37
NetP2_38: P2.38 U3.60 | length 10.3
  Top Layer w0.254: U3.60 112.065,20.691 113.081,19.675 118.745,19.675 P2.38
NetP2_39: P2.39 U3.57 | length 10.5
  Bottom Layer w0.254: U3.57 108.331,18.151 108.331,18.405 109.347,19.421 116.459,19.421 P2.39
NetP2_40: P2.40 U3.58 | length 10.8
  Top Layer w0.254: U3.58 110.871,18.151 110.871,17.897 112.014,16.754 118.364,16.754 P2.40
NetP3_5: P3.5 U3.5 | length 10.6
  Bottom Layer w0.254: P3.5 61.329,62.208 68.211,62.208 68.85,61.569 69.739,61.569 U3.5
NetP3_6: P3.6 U3.6 | length 10.7
  Top Layer w0.254: P3.6 63.754,60.061 71.247,60.061 U3.6
NetP3_7: P3.7 U3.7 | length 10.7
  Bottom Layer w0.254: P3.7 61.468,59.807 68.961,59.807 U3.7
NetP3_8: P3.8 U3.8 | length 10.8
  Top Layer w0.254: P3.8 63.881,57.394 71.12,57.394 U3.8
NetP3_9: P3.9 U3.9 | length 10.9
  Bottom Layer w0.254: P3.9 60.281,55.997 61.214,56.93 61.214,56.982 61.626,57.394 68.834,57.394 U3.9
NetP3_10: P3.10 U3.10 | length 10.6
  Top Layer w0.254: P3.10 63.615,55.12 71.386,55.12 U3.10
NetP3_11: P3.11 U3.11 | length 10.8
  Bottom Layer w0.254: P3.11 61.595,54.854 68.834,54.854 U3.11
NetP3_12: P3.12 U3.12 | length 10.6
  Top Layer w0.254: P3.12 63.627,52.568 71.374,52.568 U3.12
NetP3_13: P3.13 U3.13 | length 10.8
  Bottom Layer w0.254: P3.13 61.595,52.314 68.834,52.314 U3.13
NetP3_14: P3.14 U3.14 | length 10.7
  Top Layer w0.254: P3.14 63.754,49.901 71.247,49.901 U3.14
NetP3_15: P3.15 U3.15 | length 10.8
  Bottom Layer w0.254: P3.15 61.329,49.508 69.1,49.508 69.723,48.885 69.977,48.885 U3.15
NetP3_16: P3.16 U3.16 | length 10.7
  Top Layer w0.254: P3.16 63.754,47.361 71.247,47.361 U3.16
NetP3_17: P3.17 U3.17 | length 10.7
  Bottom Layer w0.254: P3.17 61.468,47.107 68.961,47.107 U3.17
NetP3_18: P3.18 U3.18 | length 10.7
  Top Layer w0.254: P3.18 63.754,44.821 71.247,44.821 U3.18
NetP3_19: P3.19 U3.19 | length 10.8
  Bottom Layer w0.254: P3.19 61.329,44.428 69.1,44.428 69.723,43.805 69.977,43.805 U3.19
NetP3_20: P3.20 U3.20 | length 10.6
  Top Layer w0.254: P3.20 63.627,42.408 71.374,42.408 U3.20
NetP3_21: P3.21 U3.21 | length 10.6
  Bottom Layer w0.254: P3.21 61.329,41.888 69.1,41.888 U3.21
NetP3_22: P3.22 U3.22 | length 10.9
  Top Layer w0.254: P3.22 62.841,40.757 63.996,39.602 70.445,39.602 70.497,39.551 71.056,39.551 U3.22
NetP3_23: P3.23 U3.23 | length 10.9
  Bottom Layer w0.254: P3.23 61.468,39.487 68.961,39.487 69.723,38.725 69.977,38.725 U3.23
NetP3_24: P3.24 U3.24 | length 10.7
  Top Layer w0.254: P3.24 63.754,37.201 71.247,37.201 U3.24
NetP3_25: P3.25 U3.25 | length 10.8
  Bottom Layer w0.254: P3.25 61.531,37.011 68.897,37.011 U3.25
NetP3_26: P3.26 U3.26 | length 10.8
  Top Layer w0.254: P3.26 63.881,34.534 71.12,34.534 U3.26
NetP3_27: P3.27 U3.27 | length 10.7
  Bottom Layer w0.254: P3.27 61.468,34.407 68.961,34.407 U3.27
NetP3_28: P3.28 U3.28 | length 10.6
  Top Layer w0.254: P3.28 63.627,32.248 71.374,32.248 U3.28
NetP3_29: P3.29 U3.29 | length 10.8
  Bottom Layer w0.254: P3.29 60.313,30.597 61.722,32.006 68.822,32.006 U3.29
NetP3_30: P3.30 U3.30 | length 10.8
  Top Layer w0.254: P3.30 63.881,29.454 71.12,29.454 U3.30
NetP3_31: P3.31 U3.31 | length 10.8
  Bottom Layer w0.254: P3.31 61.595,29.454 68.834,29.454 U3.31
NetP3_32: P3.32 U3.32 | length 10.7
  Top Layer w0.254: P3.32 63.754,27.041 71.247,27.041 U3.32
NetP3_33: P3.33 U3.33 | length 10.8
  Bottom Layer w0.254: P3.33 61.595,26.914 68.834,26.914 U3.33
NetP3_34: P3.34 U3.34 | length 10.9
  Top Layer w0.254: P3.34 63.754,24.501 71.247,24.501 72.263,25.517 72.263,25.771 U3.34
NetP3_35: P3.35 U3.35 | length 10.7
  Bottom Layer w0.254: P3.35 61.468,24.247 68.961,24.247 U3.35
NetP3_36: P3.36 U3.36 | length 10.9
  Top Layer w0.254: P3.36 64.008,21.707 67.501,21.707 67.882,22.088 70.433,22.088 71.386,23.041 72.327,23.041 U3.36
NetP3_37: P3.37 U3.37 | length 10.8
  Bottom Layer w0.254: P3.37 61.595,21.834 68.834,21.834 U3.37
NetP3_38: P3.38 U3.38 | length 11
  Top Layer w0.254: P3.38 64.135,19.04 69.215,19.04 69.596,19.421 71.247,19.421 U3.38
NetP3_39: P3.39 U3.39 | length 10.7
  Bottom Layer w0.254: P3.39 61.468,19.167 68.961,19.167 U3.39
NetP3_40: P3.40 U3.40 | length 11.1
  Bottom Layer w0.254: P3.40 64.262,16.373 70.739,16.373 U3.40
NetP4_1: P4.1 U3.41 | length 9.5
  Top Layer w0.254: P4.1 72.759,10.519 72.759,14.202 75.057,16.5 U3.41
NetP4_2: P4.2 U3.42 | length 12
  Top Layer w0.254: P4.2 76.327,11.547 76.327,18.532 75.295,19.564 75.295,20.199 75.057,20.437 U3.42
NetP4_3: P4.3 U3.43 | length 8.4
  Top Layer w0.254: P4.3 77.216,13.452 77.597,13.833 U3.43
NetP4_4: P4.4 U3.44 | length 11.7
  Top Layer w0.254: U3.44 78.994,19.294 78.994,10.733 79.756,9.971 P4.4
NetP4_5: P4.5 U3.45 | length 9.1
  Top Layer w0.254: U3.45 80.137,13.579 82.296,11.42 P4.5
NetP4_6: P4.6 U3.46 | length 12.7
  Top Layer w0.254: U3.46 81.534,19.294 81.534,13.198 P4.6
NetP4_7: P4.7 U3.47 | length 10.9
  Top Layer w0.254: U3.47 83.947,18.151 87.376,14.722 P4.7
NetP4_8: P4.8 U3.48 | length 15.7
  Top Layer w0.254: U3.48 85.852,20.691 89.916,16.627 P4.8
NetP4_9: P4.9 U3.49 | length 13.8
  Top Layer w0.254: P4.9 92.456,16.5 96.647,20.691 U3.49
NetP4_10: P4.10 U3.50 | length 9.6
  Top Layer w0.254: P4.10 94.869,10.023 94.869,15.103 U3.50
NetP4_11: P4.11 U3.51 | length 12
  Top Layer w0.254: P4.11 97.536,11.801 99.326,13.591 99.326,18.619 100.267,19.56 100.267,20.247 100.457,20.437 U3.51
NetP4_12: P4.12 U3.52 | length 8.4
  Top Layer w0.254: P4.12 100.266,10.087 100.266,17.961 U3.52
NetP4_13: P4.13 U3.53 | length 11.6
  Top Layer w0.254: P4.13 102.616,9.971 101.854,10.733 101.854,19.548 U3.53
NetP4_14: P4.14 U3.54 | length 9.1
  Top Layer w0.254: U3.54 105.156,15.992 P4.14
NetP4_15: P4.15 U3.55 | length 11.7
  Top Layer w0.254: U3.55 106.807,19.421 106.807,10.785 P4.15
NetP4_16: P4.16 U3.56 | length 10.2
  Bottom Layer w0.254: U3.56 105.537,14.595 P4.16
PGND: C5.1 C6.1 J12.6 J12.7 RPG1.2
Rup1: PLED1.1 PLED2.1 R2.1 | length 10.2
  Top Layer w0.254: R2.1 49.022,63.16 49.022,65.776 PLED1.1 PLED2.1
Rup2: PLED1.2 PLED2.2 R2.2 | length 9.5
  Top Layer w0.254: R2.2 48.133,66.03 49.503,67.4 PLED1.2 PLED2.2
Rup3: PLED1.3 PLED2.3 R2.3 | length 9.1
  Top Layer w0.254: PLED2.3 PLED1.3 46.963,65.422 47.295,65.09 R2.3
Rup4: PLED1.4 PLED2.4 R2.4 | length 9.8
  Top Layer w0.254: PLED2.4 PLED1.4 44.423,65.243 46.457,63.209 R2.4
RX1: J11.1 R1.1 U1.1 | length 9.4
  Top Layer w0.254: J11.1 18.059,51.552 18.059,57.29 18.415,57.646 18.415,59.352 18.989,59.926 U1.1
RX2: J5.1 R7.1 U2.1 | length 9.6
  Top Layer w0.254: J5.1 32.448,52.642 32.448,57.707 R7.1 32.448,57.714 32.766,58.031 32.797,58.031 32.797,60.053 33.498,60.754 U2.1
SGND: C1.1 C2-10uf.1 C3.1 C4.1 C7.1 C8.1 D1.2 D2.2 D3.2 D4.2 J1.1 J1.2 J1.3 J1.4 J1.5 J1.6 J1.7 J1.8 J1.9 J1.10 J2.1 J2.2 J10.1 J10.2 J12.5 P3.1 P3.3 pad.4 R4.1 R9.1 RPG1.1 S1.1 S1.2 S1.3 S1.4 S1.5 S1.6 S1.7 S1.8 U1.5 U2.5 U3.1 U3.3 | length 59.4
  Top Layer w0.254: C2-10uf.1 v1(8.382,43.551) ; J2.1@12.295,77.291 J2.1 ; v1(15.113,61.077) 15.113,62.97 C1.1 15.252,62.738 C1.1@15.469,62.521 ; C4.1 19.697,46.46 C3.1 ; C4.1@19.57,46.46 v1(19.57,48.492) ; U1.5 20.939,65.276 21.815,66.151 22.265,66.151 v1(22.352,66.239) ; R4.1 v1(22.606,58.41) ; v1(29.21,66.157) 30.316,66.157 C7.1 ; R9.1 37.592,58.232 v1(37.592,59.553) ; v1(43.053,37.455) 43.053,39.487 D4.2 ; v1@46.101,37.328 v1(46.101,37.455) D3.2@46.101,39.36 ; v1@49.149,37.328 v1(49.149,37.455) D2.2@49.149,39.36 ; v1(52.197,37.455) D1.2@52.197,39.487 ; S1.1 S1.2 S1.3 S1.4 S1.5 S1.6 S1.7 S1.8 v1(54.488,31.999) ; C8.1 59.436,71.872 v1(59.436,73.777)
  Top Layer w0.762: RPG1.1 8.975,77.291 J2.1@12.295,77.291
  other v2: 37.465,66.284
SW1: PSW1.1 R5.1 S1.16 | length 12.3
  Top Layer w0.254: R5.1 36.703,13.427 38.595,11.535 39.382,11.535 PSW1.1 45.461,10.912 S1.16
SW2: PSW1.2 R5.2 S1.15 | length 11.6
  Top Layer w0.254: R5.2 39.192,14.265 PSW1.2 45.461,13.452 S1.15
SW3: PSW1.3 R5.3 S1.14 | length 11.7
  Top Layer w0.254: R5.3 34.544,15.23 34.671,15.103 39.116,15.103 PSW1.3 45.461,15.992 S1.14
SW4: PSW1.4 R5.4 S1.13 | length 12.3
  Top Layer w0.254: R5.4 37.414,15.941 PSW1.4 45.461,18.532 S1.13
SW5: PSW1.5 R6.1 S1.12 | length 11.7
  Top Layer w0.254: R6.1 37.643,19.853 38.862,21.072 PSW1.5 45.461,21.072 S1.12
SW6: PSW1.6 R6.2 S1.11 | length 12.4
  Top Layer w0.254: R6.2 37.084,20.691 PSW1.6 45.461,23.612 S1.11
SW7: PSW1.7 R6.3 S1.10 | length 13.1
  Top Layer w0.254: R6.3 35.255,21.529 39.878,26.152 PSW1.7 45.461,26.152 S1.10
SW8: PSW1.8 R6.4 S1.9 | length 14.3
  Top Layer w0.254: R6.4 34.517,22.367 39.767,27.616 39.767,28.454 PSW1.8 45.461,28.692 S1.9
TX1: J11.3 U1.4 | length 12.4
  Top Layer w0.254: U1.4 20.939,60.144 21.03,60.053 23.503,60.053 24.511,59.045 24.511,55.108 23.266,53.863 J11.3
TX2: J5.3 U2.4 | length 13.7
  Top Layer w0.254: U2.4 35.448,60.972 35.539,60.881 38.423,60.881 39.624,59.68 39.624,57.65 37.14,55.167 37.14,52.903 37.465,52.578 J5.3
VCC-Motor: C5.2 C6.2 J2.6 J10.6 S2.3 | length 44.6
  POWER w0.508: 38.291,75.619 38.504,75.832
  POWER w1.016: v2(13.589,65.276) 18.159,65.276 18.314,65.121 23.475,65.121 33.032,74.678 37.35,74.678 38.291,75.619 ; 38.504,75.832 J10.6
  POWER w1.27: v2(13.589,66.919) 13.589,69.713 20.218,76.342 J2.6
  other v2: 10.795,60.188 12.469,60.188
VCC_3.3V: C3.2 C4.2 J4.1 J4.2 J4.3 J4.4 J4.5 J4.6 J4.7 J4.8 J4.9 J4.10 J12.2 | length 50.7
  Top Layer w0.254: J4.2 J4.2@24.384,38.727
  Top Layer w0.508: v2(23.266,43.546) 23.266,39.845 J4.2@24.384,38.727
  POWER w0.508: J12.2 4.387,49.901 8.832,45.456 16.891,45.456 19.05,43.297 20.931,43.297 21.18,43.546 v2(23.266,43.546) ; J4.10 J4.9 J4.8 J4.7 J4.6 J4.5 J4.4 J4.3 J4.2 J4.1
VCC_5V: C1.2 C2-10uf.2 C7.2 C8.2 J2.5 J3.1 J3.2 J3.3 J3.4 J3.5 J3.6 J3.7 J3.8 J3.9 J3.10 J10.5 J12.1 P3.2 P3.4 R1.2 R2.5 R2.6 R2.7 R2.8 R5.5 R5.6 R5.7 R5.8 R6.5 R6.6 R6.7 R6.8 R7.2 U1.8 U2.8 U3.2 U3.4 | length 220.6
  Top Layer w0.254: J12.1 J12.1@4.086,47.212 ; J3.10 J3.10@4.064,28.565 ; C2-10uf.2@4.445,43.401 C2-10uf.2 ; R1.2 v1(16.51,59.934) 16.51,62.867 C1.2 17.175,63.532 17.175,64.409 17.324,64.558 18.899,64.558 18.952,64.611 U1.8@18.952,65.239 ; J2.5 18.718,78.271 ; R7.2 30.734,57.76 v1(30.734,60.442) 30.734,62.521 31.454,63.241 31.454,65.673 C7.2 31.877,66.077 32.3,65.654 U2.8
  Top Layer w0.508: J12.1@4.086,47.212 4.086,43.91 C2-10uf.2 ; 18.718,78.271 19.431,78.984 21.717,78.984 22.86,77.841 v2(22.86,72.126) 22.86,71.872 25.527,69.205 v2(25.527,61.712)
  POWER w0.508: v2(2.794,41.679) 1.397,40.282 1.397,31.232 4.064,28.565 J3.10 J3.9 J3.8 J3.7 J3.6 J3.5 J3.4 J3.3 J3.2 J3.1 30.099,28.311 30.734,27.676 v2(30.734,21.072) ; v2(10.033,41.265) 24.605,41.265 27.94,44.6 27.94,59.299 v2(25.527,61.712) v2@25.527,61.839 ; v1(16.51,59.934) 18.415,61.839 v2@25.527,61.839 ; v2(22.86,72.126) 22.987,72.126 27.051,76.19 27.051,77.587 28.575,79.111 35.353,79.111 J10.5 ; U3.4 U3.2 68.453,70.475 63.527,70.475 61.749,68.697 v1(55.372,68.697) 55.372,66.285 v1(48.812,59.726) 47.37,58.283 32.893,58.283 v1(30.734,60.442) 30.695,60.481 30.695,60.989 29.845,61.839 v2@25.527,61.839
  other v1: 55.372,70.245
  other v2: 30.861,14.849
VCC_12V: J12.3 J12.4 S2.2
  other v2: 7.112,52.187 7.112,54.473
pads on no net: S2.1

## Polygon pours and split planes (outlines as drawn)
SGND on Top Layer "Top Layer-SGND 2" (solid, pour order 56): 124.968,85.852 124.968,80.01 0,80.01 0,85.979
no net on Top Layer "Top Layer-No Net 1" (solid, pour order 54): 0,85.979
VCC_5V on Top Layer "Top Layer-VCC_5V 1" (solid, pour order 32): 1.778,47.234 2.667,48.123 2.667,48.631 4.826,48.631 5.715,47.742 5.715,45.202 5.207,44.694 5.334,44.567 5.334,42.535 5.461,42.535 5.842,42.154 5.842,42.027 15.591,42.027 15.718,42.154 17.018,40.854 17.018,40.503 16.764,40.249 16.637,40.376 2.286,40.376 1.778,40.884
VCC-Motor on Top Layer "Top Layer-VCC-Motor 1" (solid, pour order 26): 6.858,67.173 7.493,67.808 7.493,68.062 11.811,68.062 13.97,65.903 13.97,55.743 13.208,54.981 9.906,54.981 6.858,58.029
VCC_12V on Top Layer "Top Layer-VCC_12V" (solid, pour order 22): 1.905,55.616 2.667,56.378 8.128,56.378 9.271,55.235 9.271,54.346 9.779,53.838 13.589,53.838 14.097,53.33 14.097,51.044 13.208,50.155 7.239,50.155 6.096,51.298 2.286,51.298 1.905,51.679
SGND on Top Layer "Top Layer-SGND 1" (solid, pour order 48): 0,80.01 0,71.374 12.446,71.374 13.335,70.485 13.335,67.935 6.858,61.458 6.858,58.41 0.117,58.41 0,58.293 0,0.127 125.095,0.127 124.968,0.254 124.968,80.01
PGND on Top Layer "Top Layer-PGND 1" (solid, pour order 46): 0,71.12 12.319,71.12 13.081,70.358 13.081,62.357 9.842,62.357 6.159,58.674 0.508,58.674 0.508,58.687 0,59.195
VCC_3.3V on Top Layer "Top Layer-VCC_3.3V" (solid, pour order 36): 17.78,45.075 18.415,45.71 23.368,45.71 24.003,45.075 23.876,44.948 23.876,43.17 23.431,42.726 19.113,42.726 17.78,44.059
VCC_5V on Top Layer "Top Layer-VCC_5V" (solid, pour order 34): 8.763,42.091 10.033,43.361 10.033,43.932 15.494,43.932 17.018,42.408 17.018,40.679 16.559,41.138 9.144,41.138
no net on Top Layer "Top Layer-No Net" (solid, pour order 30): 3.429,44.313
VCC-Motor on Top Layer "Top Layer-VCC-Motor" (solid, pour order 28): 12.003,67.704 14.351,67.704 14.986,67.069 14.986,65.395 13.716,64.125 13.716,63.871 12.511,63.871 12.003,64.379 11.938,64.379
PGND on Top Layer "Top Layer-PGND" (solid, pour order 24): 1.143,68.189 2.413,69.459 2.413,70.475 10.797,70.475 12.319,68.953 12.295,68.93 12.295,68.189 7.239,68.189 5.945,66.895 5.945,59.726 5.888,59.726 4.826,58.664 2.078,58.664 1.016,59.726
VCC_5V on Top Layer "Top Layer-VCC_5V 2" (solid, pour order 12): 30.377,23.866 32.512,23.866 33.655,22.723 33.655,12.944 33.02,12.309 30.099,12.309 29.21,13.198 29.21,22.723 29.337,22.85
VCC_5V on Top Layer "Top Layer-VCC_5V 3" (solid, pour order 8): 53.721,70.348 54.61,71.237 57.616,71.237 58.039,70.814 58.039,68.316 57.231,67.508 54.864,67.508 54.864,67.542 53.721,68.685
VCC_5V on Top Layer "Top Layer-VCC_5V 4" (solid, pour order 6): 56.515,70.094 57.531,71.11 63.119,71.11 65.024,69.205 65.024,67.681 65.036,67.681 65.532,67.185 65.532,64.125 63.881,62.474 58.293,62.474 56.515,64.252
VCC_5V on Top Layer "Top Layer-VCC_5V 5" (solid, pour order 4): 45.466,61.331 45.593,61.331 46.228,61.966 50.165,61.966 50.673,61.458 50.673,59.807 50.038,59.172 46.35,59.172 45.588,59.934 45.466,59.934
SGND on Top Layer "Top Layer-SGND" (solid, pour order 0): 35.179,66.665 35.56,67.046 35.56,67.173 38.481,67.173 38.862,66.792 38.862,65.372 38.504,65.014 35.687,65.014 35.179,65.522
no net on POWER "POWER-No Net" (solid, pour order 38): 14.224,67.681
no net on Mechanical 1 (solid): 0,70.866
PGND on Bottom Layer "Bottom Layer-PGND" (solid, pour order 52): 0,71.12 12.319,71.12 13.081,70.358 13.081,62.357 9.842,62.357 6.159,58.674 0.508,58.674 0.508,58.687 0,59.195
SGND on Bottom Layer "Bottom Layer-SGND" (solid, pour order 50): 0,80.01 0,71.374 12.446,71.374 13.335,70.485 13.335,67.935 6.858,61.458 6.858,58.41 0.117,58.41 0,58.293 0,0.127 125.095,0.127 124.968,0.254 124.968,80.01
PGND on GND (split plane): 12.822,70.376 12.699,65.332 8.556,62.068 8.544,62.054 8.53,62.041 6.41,59.047 0.51,59.047 0.51,70.727 6.096,70.727 6.098,70.727 6.1,70.727 10.467,70.878 10.516,70.889 10.557,70.919 10.584,70.962 10.584,70.965
SGND on GND (split plane): 124.49,85.358 124.489,0.379 0.51,0.51 0.51,58.789 6.477,58.789 6.488,58.791 6.499,58.79 6.512,58.796 6.527,58.798 6.536,58.804 6.546,58.808 6.557,58.818 6.569,58.826 6.575,58.836 6.583,58.843 8.731,61.876 12.907,65.166 12.911,65.171 12.916,65.174 12.927,65.19 12.94,65.205 12.942,65.211 12.945,65.216 12.95,65.234 12.956,65.253 12.955,65.259 12.956,65.265 13.083,70.472 13.082,70.482 13.082,70.492 13.077,70.507 13.075,70.522 13.069,70.53 13.066,70.54 13.056,70.552 13.048,70.564 13.039,70.57 13.032,70.578 13.019,70.585 13.006,70.593 12.996,70.596 12.987,70.6 10.574,71.235 10.524,71.238 10.476,71.222 10.438,71.188 10.416,71.143 10.415,71.135 6.094,70.985 0.51,70.985 0.51,85.489

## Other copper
Top Layer:
  pour cut-out: 9.553,55.1 9.622,55.1 9.906,54.816 9.847,54.757 9.847,54.341 10.096,54.092 10.096,54.003 9.847,54.003 9.436,54.414 9.436,55.052
  text "北京理工大学-牛牛队-2021-主控板-Ver1" at 14.356,83 h1.52
GND (plane layer: these items are gaps in the copper):
  lines w0.254: -0.127,58.918 6.477,58.918 8.636,61.966 12.827,65.268 12.954,70.475 10.541,71.11 ; 5.08,70.856 -0.127,70.856 6.096,70.856 10.463,71.007

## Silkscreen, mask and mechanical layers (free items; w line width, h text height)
Mechanical 1:
  the board outline again, w0.254

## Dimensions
124.968,85.852 to 124.968,0.254 on Top Layer
0,0 to 125,-0.132 on Mechanical 1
